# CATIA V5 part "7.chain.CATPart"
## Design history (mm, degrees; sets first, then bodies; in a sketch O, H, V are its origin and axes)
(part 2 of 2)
    arc A128 centre (-268.5287, -40.189) radius 4.5 from (-270.462, -44.2525) to (-269.3408, -35.7629) ccw
    arc A129 centre (-272.0479, -21.0092) radius 15 from (-278.4922, -34.5543) to (-269.3408, -35.7629) ccw
    arc A130 centre (-276.9062, -57.7977) radius 15 from (-279.6133, -43.044) to (-270.462, -44.2525) cw
    circle A131 centre (-268.5287, -40.189) radius 2.25
    circle A132 centre (-280.4254, -38.6179) radius 2.25
    point P217 (-292.3221, -37.0468)
    point P218 (-292.8074, -27.8588)
    arc A133 centre (-304.2189, -35.4757) radius 4.5 from (-302.2856, -31.4122) to (-303.4067, -39.9018) ccw
    arc A134 centre (-292.3221, -37.0468) radius 4.5 from (-294.2554, -41.1104) to (-293.1343, -32.6207) ccw
    arc A135 centre (-295.8413, -17.867) radius 15 from (-302.2856, -31.4122) to (-293.1343, -32.6207) ccw
    arc A136 centre (-300.6997, -54.6555) radius 15 from (-303.4067, -39.9018) to (-294.2554, -41.1104) cw
    circle A137 centre (-292.3221, -37.0468) radius 2.25
    circle A138 centre (-304.2189, -35.4757) radius 2.25
    point P227 (-316.1156, -33.9046)
    point P228 (-316.6009, -24.7166)
    arc A139 centre (-328.0123, -32.3335) radius 4.5 from (-326.079, -28.27) to (-327.2001, -36.7596) ccw
    arc A140 centre (-316.1156, -33.9046) radius 4.5 from (-318.0488, -37.9682) to (-316.9277, -29.4785) ccw
    arc A141 centre (-319.6347, -14.7248) radius 15 from (-326.079, -28.27) to (-316.9277, -29.4785) ccw
    arc A142 centre (-324.4931, -51.5133) radius 15 from (-327.2001, -36.7596) to (-318.0488, -37.9682) cw
    circle A143 centre (-316.1156, -33.9046) radius 2.25
    circle A144 centre (-328.0123, -32.3335) radius 2.25
    point P237 (-339.909, -30.7624)
    point P238 (-340.3943, -21.5744)
    arc A145 centre (-351.7634, -28.8988) radius 4.5 from (-349.7306, -24.8841) to (-351.0605, -33.3436) ccw
    arc A146 centre (-339.909, -30.7624) radius 4.5 from (-341.9417, -34.7771) to (-340.6118, -26.3177) ccw
    arc A147 centre (-342.9548, -11.5018) radius 15 from (-349.7306, -24.8841) to (-340.6118, -26.3177) ccw
    arc A148 centre (-348.7176, -48.1595) radius 15 from (-351.0605, -33.3436) to (-341.9417, -34.7771) cw
    circle A149 centre (-339.909, -30.7624) radius 2.25
    circle A150 centre (-351.7634, -28.8988) radius 2.25
    reference projected circle E7 centre (-351.7634, -28.8988) radius 2.25 from edge [face of Pad1 from Sketch2.A51 | end face of Pad1]
    reference projected circle E8 centre (-339.909, -30.7624) radius 2.25 from edge [face of Pad1 from Sketch2.A50 | end face of Pad1]
    point P241 (-373.5862, -2.7223)
    reference projected circle E9 centre (-373.5862, -2.7223) radius 2.25 from edge [face of Pad1 from Sketch2.A55 | end face of Pad1]
    reference projected circle E10 centre (-362.4451, -23.4307) radius 2.25 from edge [face of Pad1 from Sketch2.A53 | end face of Pad1]
    reference projected circle E11 centre (-370.1292, -14.2136) radius 2.25 from edge [face of Pad1 from Sketch2.A54 | end face of Pad1]
    construction circle A151 centre (-343.71, 0) radius 3.5746
    reference projected arc E12 centre (-343.71, 0) radius 30 from (-347.6377, 29.7418) to (-347.6377, -29.7418) ccw from Sketch1.A2
    arc A152 centre (-372.2631, 9.2045) radius 4.5 from (-368.1602, 7.3562) to (-376.6713, 8.3004) ccw
    arc A153 centre (-354.4838, 1.1953) radius 15 from (-368.1602, 7.3562) to (-369.178, -1.8183) ccw
    arc A154 centre (-391.3655, 5.2869) radius 15 from (-376.6713, 8.3004) to (-377.6891, -0.874) cw
    arc A155 centre (-373.5862, -2.7223) radius 4.5 from (-377.6891, -0.874) to (-369.178, -1.8183) ccw
    circle A156 centre (-373.5862, -2.7223) radius 2.25
    circle A157 centre (-372.2631, 9.2045) radius 2.25
    arc A158 centre (-356.8539, 26.9673) radius 4.5 from (-355.3443, 22.7281) to (-360.5599, 29.5199) ccw
    arc A159 centre (-350.3122, 8.5974) radius 15 from (-355.3443, 22.7281) to (-362.6654, 17.106) ccw
    arc A160 centre (-372.9132, 38.0286) radius 15 from (-360.5599, 29.5199) to (-367.881, 23.8978) cw
    arc A161 centre (-366.3714, 19.6586) radius 4.5 from (-367.881, 23.8978) to (-362.6654, 17.106) ccw
    circle A162 centre (-366.3714, 19.6586) radius 2.25
    circle A163 centre (-356.8539, 26.9673) radius 2.25
    arc A164 centre (-345.2582, 30.056) radius 4.5 from (-344.4461, 34.4821) to (-343.3249, 25.9925) ccw
    circle A165 centre (-345.2582, 30.056) radius 2.25
    arc A166 centre (-333.3615, 31.6271) radius 4.5 from (-334.1736, 27.201) to (-335.2948, 35.6907) ccw
    circle A167 centre (-333.3615, 31.6271) radius 2.25
    arc A168 centre (-341.739, 49.2358) radius 15 from (-344.4461, 34.4821) to (-335.2948, 35.6907) ccw
    arc A169 centre (-336.8807, 12.4473) radius 15 from (-343.3249, 25.9925) to (-334.1736, 27.201) cw
    arc A170 centre (-81.1513, 64.9343) radius 4.5 from (-80.0516, 69.2978) to (-78.9565, 61.0058) ccw
    arc A171 centre (-66.8752, 66.8196) radius 4.5 from (-67.975, 62.456) to (-69.07, 70.748) ccw
    arc A172 centre (-76.3859, 83.843) radius 15 from (-80.0516, 69.2978) to (-69.07, 70.748) ccw
    arc A173 centre (-71.6406, 47.9108) radius 15 from (-78.9565, 61.0058) to (-67.975, 62.456) cw
    circle A174 centre (-66.8752, 66.8196) radius 2.25
    circle A175 centre (-81.1513, 64.9343) radius 2.25
    reference projected circle E13 centre (-345.2582, 30.056) radius 2.25 from edge [face of Pad1 from Sketch2.A59 | end face of Pad1]
    reference projected circle E14 centre (-333.3615, 31.6271) radius 2.25 from edge [face of Pad1 from Sketch2.A60 | end face of Pad1]
    point P275 (-321.4648, 33.1982)
    reference projected circle E15 centre (-321.4648, 33.1982) radius 2.25 from edge [face of Pad1 from Sketch2.A61 | end face of Pad1]
    arc A176 centre (-321.4648, 33.1982) radius 4.5 from (-320.6527, 37.6243) to (-319.5315, 29.1346) ccw
    circle A177 centre (-321.4648, 33.1982) radius 2.25
    arc A178 centre (-309.5681, 34.7693) radius 4.5 from (-310.3802, 30.3432) to (-311.5014, 38.8328) ccw
    circle A179 centre (-309.5681, 34.7693) radius 2.25
    arc A180 centre (-317.9456, 52.378) radius 15 from (-320.6527, 37.6243) to (-311.5014, 38.8328) ccw
    arc A181 centre (-313.0873, 15.5895) radius 15 from (-319.5315, 29.1346) to (-310.3802, 30.3432) cw
    arc A182 centre (-297.6714, 36.3404) radius 4.5 from (-296.8593, 40.7665) to (-295.7381, 32.2768) ccw
    circle A183 centre (-297.6714, 36.3404) radius 2.25
    arc A184 centre (-285.7747, 37.9115) radius 4.5 from (-286.5868, 33.4854) to (-287.708, 41.975) ccw
    circle A185 centre (-285.7747, 37.9115) radius 2.25
    arc A186 centre (-294.1522, 55.5202) radius 15 from (-296.8593, 40.7665) to (-287.708, 41.975) ccw
    arc A187 centre (-289.2939, 18.7317) radius 15 from (-295.7381, 32.2768) to (-286.5868, 33.4854) cw
    arc A188 centre (-273.878, 39.4826) radius 4.5 from (-273.0659, 43.9087) to (-271.9447, 35.419) ccw
    circle A189 centre (-273.878, 39.4826) radius 2.25
    arc A190 centre (-261.9813, 41.0537) radius 4.5 from (-262.7934, 36.6275) to (-263.9145, 45.1172) ccw
    circle A191 centre (-261.9813, 41.0537) radius 2.25
    arc A192 centre (-270.3588, 58.6624) radius 15 from (-273.0659, 43.9087) to (-263.9145, 45.1172) ccw
    arc A193 centre (-265.5005, 21.8738) radius 15 from (-271.9447, 35.419) to (-262.7934, 36.6275) cw
    arc A194 centre (-250.0846, 42.6247) radius 4.5 from (-249.2724, 47.0509) to (-248.1513, 38.5612) ccw
    circle A195 centre (-250.0846, 42.6247) radius 2.25
    arc A196 centre (-238.1878, 44.1958) radius 4.5 from (-239, 39.7697) to (-240.1211, 48.2594) ccw
    circle A197 centre (-238.1878, 44.1958) radius 2.25
    arc A198 centre (-246.5654, 61.8046) radius 15 from (-249.2724, 47.0509) to (-240.1211, 48.2594) ccw
    arc A199 centre (-241.707, 25.016) radius 15 from (-248.1513, 38.5612) to (-239, 39.7697) cw
    arc A200 centre (-226.2911, 45.7669) radius 4.5 from (-225.479, 50.193) to (-224.3579, 41.7034) ccw
    circle A201 centre (-226.2911, 45.7669) radius 2.25
    arc A202 centre (-214.3944, 47.338) radius 4.5 from (-215.2066, 42.9119) to (-216.3277, 51.4016) ccw
    circle A203 centre (-214.3944, 47.338) radius 2.25
    arc A204 centre (-222.772, 64.9467) radius 15 from (-225.479, 50.193) to (-216.3277, 51.4016) ccw
    arc A205 centre (-217.9136, 28.1582) radius 15 from (-224.3579, 41.7034) to (-215.2066, 42.9119) cw
    arc A206 centre (-202.4977, 48.9091) radius 4.5 from (-201.6856, 53.3352) to (-200.5644, 44.8456) ccw
    circle A207 centre (-202.4977, 48.9091) radius 2.25
    arc A208 centre (-190.601, 50.4802) radius 4.5 from (-191.4131, 46.0541) to (-192.5343, 54.5438) ccw
    circle A209 centre (-190.601, 50.4802) radius 2.25
    arc A210 centre (-198.9785, 68.0889) radius 15 from (-201.6856, 53.3352) to (-192.5343, 54.5438) ccw
    arc A211 centre (-194.1202, 31.3004) radius 15 from (-200.5644, 44.8456) to (-191.4131, 46.0541) cw
    arc A212 centre (-178.7043, 52.0513) radius 4.5 from (-177.8922, 56.4774) to (-176.771, 47.9877) ccw
    circle A213 centre (-178.7043, 52.0513) radius 2.25
    arc A214 centre (-166.8076, 53.6224) radius 4.5 from (-167.6197, 49.1963) to (-168.7409, 57.6859) ccw
    circle A215 centre (-166.8076, 53.6224) radius 2.25
    arc A216 centre (-175.1851, 71.2311) radius 15 from (-177.8922, 56.4774) to (-168.7409, 57.6859) ccw
    arc A217 centre (-170.3268, 34.4426) radius 15 from (-176.771, 47.9877) to (-167.6197, 49.1963) cw
    arc A218 centre (-154.9109, 55.1935) radius 4.5 from (-154.0988, 59.6196) to (-152.9776, 51.1299) ccw
    circle A219 centre (-154.9109, 55.1935) radius 2.25
    arc A220 centre (-143.0142, 56.7646) radius 4.5 from (-143.8263, 52.3385) to (-144.9475, 60.8281) ccw
    circle A221 centre (-143.0142, 56.7646) radius 2.25
    arc A222 centre (-151.3917, 74.3733) radius 15 from (-154.0988, 59.6196) to (-144.9475, 60.8281) ccw
    arc A223 centre (-146.5334, 37.5848) radius 15 from (-152.9776, 51.1299) to (-143.8263, 52.3385) cw
    arc A224 centre (-131.1175, 58.3357) radius 4.5 from (-130.3054, 62.7618) to (-129.1842, 54.2721) ccw
    circle A225 centre (-131.1175, 58.3357) radius 2.25
    arc A226 centre (-119.2208, 59.9068) radius 4.5 from (-120.0329, 55.4806) to (-121.154, 63.9703) ccw
    circle A227 centre (-119.2208, 59.9068) radius 2.25
    arc A228 centre (-127.5983, 77.5155) radius 15 from (-130.3054, 62.7618) to (-121.154, 63.9703) ccw
    arc A229 centre (-122.74, 40.7269) radius 15 from (-129.1842, 54.2721) to (-120.0329, 55.4806) cw
    arc A230 centre (-107.3241, 61.4778) radius 4.5 from (-106.5119, 65.904) to (-105.3908, 57.4143) ccw
    circle A231 centre (-107.3241, 61.4778) radius 2.25
    arc A232 centre (-95.4273, 63.0489) radius 4.5 from (-96.2395, 58.6228) to (-97.3606, 67.1125) ccw
    circle A233 centre (-95.4273, 63.0489) radius 2.25
    arc A234 centre (-103.8049, 80.6577) radius 15 from (-106.5119, 65.904) to (-97.3606, 67.1125) ccw
    arc A235 centre (-98.9465, 43.8691) radius 15 from (-105.3908, 57.4143) to (-96.2395, 58.6228) cw
    reference projected circle E16 centre (-81.1513, 64.9343) radius 2.25 from edge [face of Pad1 from Sketch2.A81 | end face of Pad1]
    reference projected circle E17 centre (-66.8752, 66.8196) radius 2.25 from edge [face of Pad1 from Sketch2.A82 | end face of Pad1]
    point P356 (-52.5992, 68.7049)
    reference projected circle E18 centre (-52.5992, 68.7049) radius 2.25 from edge [face of Pad1 from Sketch2.A83 | end face of Pad1]
    arc A236 centre (-52.5992, 68.7049) radius 4.5 from (-51.4995, 73.0684) to (-50.4044, 64.7764) ccw
    arc A237 centre (-38.3231, 70.5902) radius 4.5 from (-39.4229, 66.2266) to (-40.5179, 74.5187) ccw
    arc A238 centre (-47.8338, 87.6136) radius 15 from (-51.4995, 73.0684) to (-40.5179, 74.5187) ccw
    arc A239 centre (-43.0885, 51.6814) radius 15 from (-50.4044, 64.7764) to (-39.4229, 66.2266) cw
    circle A240 centre (-38.3231, 70.5902) radius 2.25
    circle A241 centre (-52.5992, 68.7049) radius 2.25
    arc A242 centre (-24.0471, 72.4755) radius 4.5 from (-22.9474, 76.8391) to (-21.8523, 68.547) ccw
    arc A243 centre (-9.771, 74.3608) radius 4.5 from (-10.8708, 69.9972) to (-11.9658, 78.2893) ccw
    arc A244 centre (-19.2817, 91.3842) radius 15 from (-22.9474, 76.8391) to (-11.9658, 78.2893) ccw
    arc A245 centre (-14.5364, 55.4521) radius 15 from (-21.8523, 68.547) to (-10.8708, 69.9972) cw
    circle A246 centre (-9.771, 74.3608) radius 2.25
    circle A247 centre (-24.0471, 72.4755) radius 2.25
    arc A248 centre (2.1649, 74.9687) radius 4.5 from (4.0069, 79.0745) to (3.0758, 70.5619) ccw
    circle A249 centre (2.1649, 74.9687) radius 2.25
    arc A250 centre (14.0938, 73.6639) radius 4.5 from (12.2518, 69.5581) to (13.183, 78.0707) ccw
    circle A251 centre (14.0938, 73.6639) radius 2.25
    arc A252 centre (10.1469, 92.7603) radius 15 from (4.0069, 79.0745) to (13.183, 78.0707) ccw
    arc A253 centre (6.1118, 55.8724) radius 15 from (3.0758, 70.5619) to (12.2518, 69.5581) cw
    reference projected circle E19 centre (2.1649, 74.9687) radius 2.25 from edge [face of Pad1 from Sketch2.A2 | end face of Pad1]
    reference projected circle E20 centre (14.0938, 73.6639) radius 2.25 from edge [face of Pad1 from Sketch2.A3 | end face of Pad1]
    radius A58 = 2.25
    radius A55 = 4.5
    radius A57 = 2.25
    radius A56 = 4.5
    radius A60 = 15
    radius A59 = 15
    radius A61 = 4.5
    radius A62 = 4.5
    radius A65 = 2.25
    radius A66 = 2.25
    radius A63 = 15
    radius A64 = 15
    radius A67 = 4.5
    radius A146 = 4.5
    radius A149 = 2.25
    radius A145 = 4.5
    radius A150 = 2.25
    radius A147 = 15
    radius A148 = 15
    radius A70 = 4.5
    radius A71 = 2.25
    radius A72 = 2.25
    radius A68 = 15
    radius A69 = 15
    radius A165 = 2.25
    radius A164 = 4.5
    radius A168 = 15
    radius A166 = 4.5
    radius A167 = 2.25
    radius A169 = 15
    radius A170 = 4.5
    radius A172 = 15
    radius A174 = 2.25
    radius A173 = 15
    radius A171 = 4.5
    radius A175 = 2.25
    radius A248 = 4.5
    radius A250 = 4.5
    radius A251 = 2.25
    radius A249 = 2.25 (reference)
    radius A253 = 15
    radius A252 = 15
    concentricity: P2 E1, A57 E2, A58 E3, A65 E4, A66 E5, P110 E6, A150 E7, A149 E8, P241 E9, A71 E10, E11 A72, A151 E12, A165 E13, A167 E14, P275 E15, E16 A175, A174 E17, P356 E18, A249 E19, A251 E20
    tangency: A59 A55, A60 A55, A60 A56, A59 A56, A63 A61, A64 A61, A64 A62, A63 A62, A68 A67, A69 A67, A69 A70, A68 A70, A147 A146, A147 A145, A148 A146, A148 A145, A168 A164, A169 A164, A169 A166, A168 A166, A172 A170, A173 A170, A173 A171, A172 A171, A253 A248, A250 A253, A252 A250, A252 A248
  Pad3: profile Sketch4, direction (1, 0, 0), length 2, opposite side length -1
  Mirror2: of Pad3, about yz-plane
  Sketch5 on yz-plane, origin (0, 0, 0), H (0, 1, 0), V (0, 0, 1)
